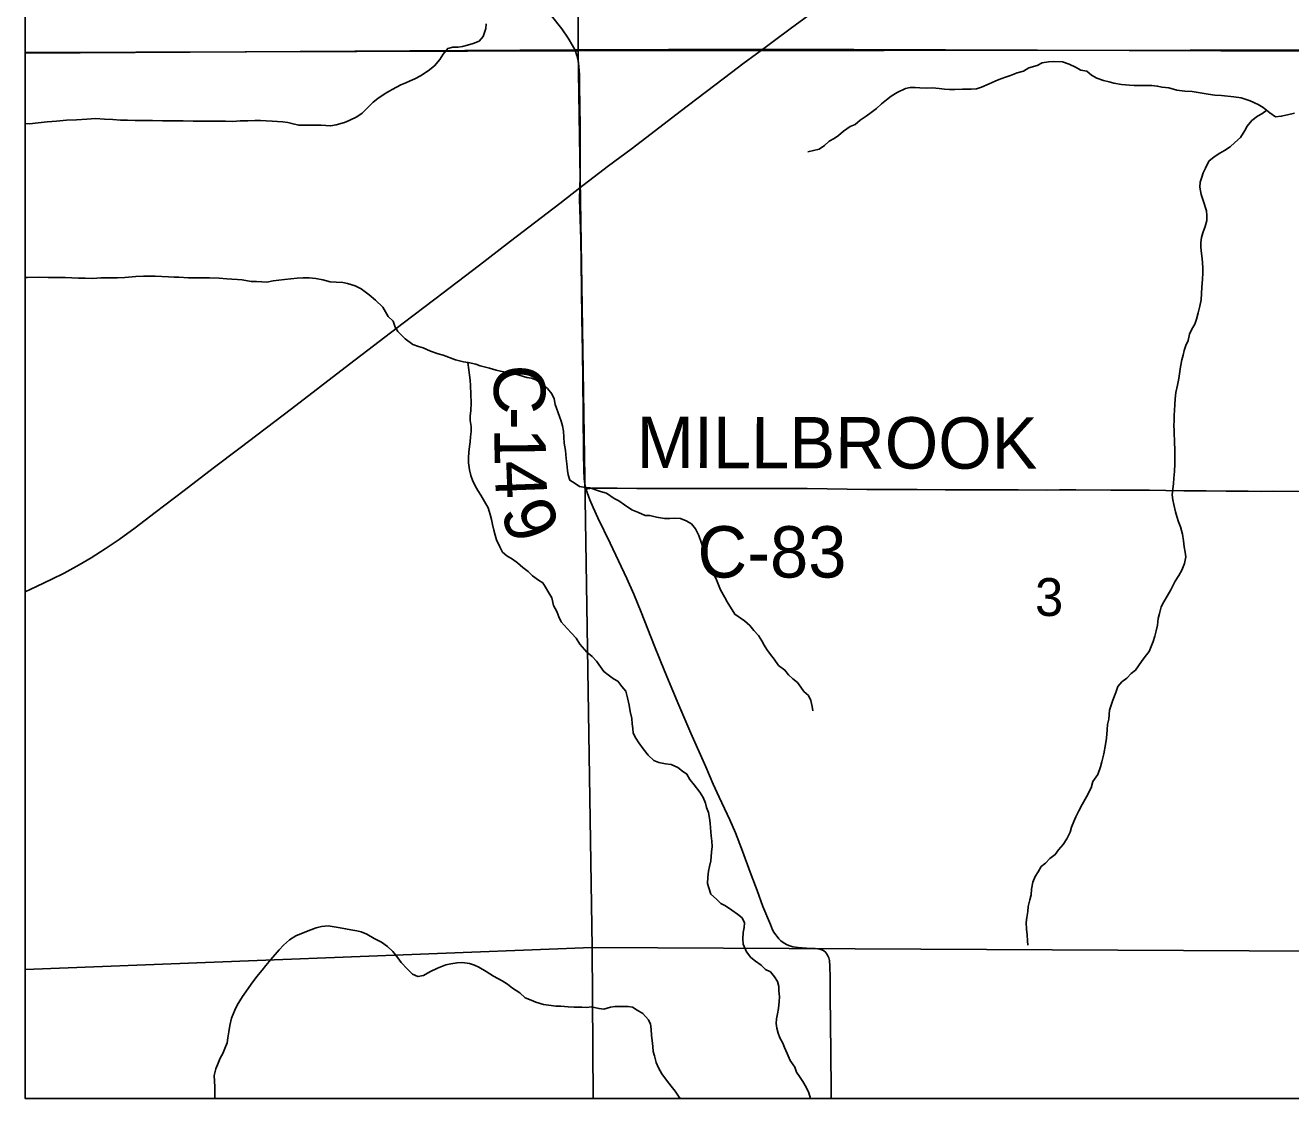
# Model space of a CAD drawing. Extents: x 0 to 34, y 0 to 22.
# Drawn here: x 2.1 to 3.5, y 14.1 to 15.287 of the extents above; entities that cross this region are included whole.
import ezdxf

# ---------------------------------------------------------------- set-up
doc = ezdxf.new("R2010")
doc.units = 0
for name, color, linetype in [('GM_X_County_Road', 7, 'Continuous'), ('GM_X_County_Road_Text', 7, 'Continuous'), ('GM_X_Minor_River', 7, 'Continuous'), ('GM_X_Section', 7, 'Continuous'), ('GM_X_Section_Text', 7, 'Continuous'), ('GM_X_State_Route', 7, 'Continuous'), ('GM_X_Township_Road', 7, 'Continuous'), ('GM_X_Unincorporated', 7, 'Continuous'), ('SH_Data', 7, 'Continuous')]:
    doc.layers.add(name, color=color, linetype=linetype)

msp = doc.modelspace()

# ---------------------------------------------------------------- linework, layer by layer
at = {"layer": 'GM_X_County_Road'}
for points in [[(2.708, 15.2591), (2.7053, 15.2645), (2.7005, 15.2725), (2.6934, 15.2826), (2.682, 15.2973)], [(2.7134, 15.1071), (2.7138, 15.1191), (2.7138, 15.1302), (2.7136, 15.1426), (2.7136, 15.1737), (2.7133, 15.1984), (2.713, 15.2197), (2.7128, 15.2321), (2.7124, 15.2413), (2.7115, 15.2474), (2.7101, 15.2533), (2.708, 15.2591)], [(2.7201, 14.774), (2.7197, 14.776), (2.7188, 14.7798), (2.718, 14.7854), (2.7176, 14.7951), (2.7172, 14.8137), (2.7169, 14.8573), (2.7167, 14.8946), (2.7161, 14.9257), (2.7157, 14.963), (2.7148, 15.0252), (2.7143, 15.05), (2.713, 15.094), (2.7134, 15.1071)], [(2.7201, 14.774), (2.7267, 14.7749), (2.7359, 14.775), (2.7545, 14.7749), (2.7762, 14.7747), (2.8352, 14.7747), (2.86, 14.7746), (2.8786, 14.7746), (2.9065, 14.7747), (2.9307, 14.7747), (2.9461, 14.7747), (2.9648, 14.7744), (3.0089, 14.7738), (3.0306, 14.7734), (3.0585, 14.7733), (3.071, 14.7733), (3.0865, 14.7733), (3.1175, 14.7731), (3.1393, 14.7732), (3.1734, 14.7732), (3.1983, 14.7732), (3.2293, 14.7729), (3.244, 14.773), (3.2618, 14.773), (3.3008, 14.7728), (3.3194, 14.7727), (3.3435, 14.7726), (3.3613, 14.7724), (3.3814, 14.7721), (3.3938, 14.772), (3.4062, 14.7719), (3.4282, 14.7717), (3.4527, 14.7716), (3.4673, 14.7714), (3.48, 14.7716), (3.5224, 14.7711)], [(2.9913, 14.1), (2.9913, 14.1135), (2.9909, 14.1468), (2.9904, 14.1872), (2.9903, 14.209), (2.9901, 14.2214), (2.9901, 14.2338), (2.99, 14.2463), (2.9894, 14.2526), (2.9887, 14.2558), (2.9874, 14.2588), (2.9854, 14.2615), (2.9828, 14.2636), (2.9799, 14.2649), (2.9767, 14.2657), (2.9735, 14.266), (2.9642, 14.2665), (2.9549, 14.2671), (2.9488, 14.268), (2.9456, 14.2691), (2.9426, 14.2701), (2.9395, 14.2718), (2.9356, 14.2746), (2.9335, 14.2768), (2.9315, 14.2791), (2.9297, 14.2815), (2.928, 14.2841), (2.9266, 14.2868), (2.9241, 14.2924), (2.9159, 14.3125), (2.9094, 14.33), (2.9028, 14.3474), (2.8922, 14.3766), (2.8854, 14.3939), (2.8792, 14.4082), (2.8675, 14.4333), (2.8609, 14.4476), (2.8526, 14.4667), (2.836, 14.5039), (2.8227, 14.535), (2.8096, 14.5666), (2.8022, 14.5848), (2.7958, 14.6004), (2.781, 14.638), (2.7729, 14.6579), (2.7653, 14.6749), (2.7467, 14.7142), (2.7333, 14.7423), (2.7282, 14.7536), (2.7245, 14.7621), (2.7213, 14.7701), (2.7201, 14.774)]]:
    msp.add_lwpolyline(points, dxfattribs=at)
at = {"layer": 'GM_X_Minor_River'}
for points in [[(2.1, 15.1781), (2.1048, 15.1779), (2.1144, 15.1787), (2.1243, 15.1798), (2.1346, 15.1806), (2.1457, 15.1817), (2.1567, 15.1821), (2.1682, 15.1828), (2.1777, 15.1836), (2.1877, 15.1828), (2.1968, 15.1824), (2.2052, 15.1817), (2.2132, 15.1817), (2.2216, 15.1813), (2.2407, 15.1813), (2.2518, 15.1809), (2.2747, 15.1809), (2.2858, 15.1805), (2.2961, 15.1805), (2.3052, 15.1808), (2.3216, 15.1808), (2.3296, 15.1804), (2.3377, 15.1812), (2.3461, 15.1812), (2.3537, 15.1816), (2.3602, 15.1816), (2.3663, 15.1812), (2.3732, 15.1808), (2.3789, 15.1804), (2.385, 15.18), (2.3903, 15.1793), (2.3961, 15.1777), (2.4025, 15.1762), (2.4201, 15.1762), (2.4274, 15.1762), (2.4323, 15.1758), (2.4377, 15.1754), (2.4438, 15.1766), (2.4529, 15.1792), (2.4583, 15.1815), (2.4666, 15.1853), (2.4727, 15.1895), (2.4781, 15.1952), (2.4849, 15.2016), (2.4899, 15.2058), (2.4979, 15.2111), (2.5059, 15.2157), (2.5154, 15.221), (2.5208, 15.2229), (2.5257, 15.2252), (2.531, 15.2275), (2.5371, 15.2309), (2.5455, 15.2362), (2.5524, 15.2419), (2.5585, 15.2487), (2.5623, 15.2548), (2.5672, 15.2609), (2.5729, 15.2624), (2.5787, 15.2624), (2.5836, 15.2632), (2.589, 15.2647), (2.5955, 15.2666), (2.6019, 15.2693), (2.6065, 15.2742), (2.6095, 15.2833), (2.6099, 15.2883)], [(3.5039, 15.1896), (3.4959, 15.1877), (3.4891, 15.1862), (3.4826, 15.1855), (3.4765, 15.19), (3.4692, 15.1957), (3.4635, 15.1992), (3.4547, 15.2033), (3.4448, 15.2064), (3.4367, 15.2075), (3.423, 15.2091), (3.4157, 15.2095), (3.4081, 15.2106), (3.3993, 15.2121), (3.3905, 15.2133), (3.3825, 15.2137), (3.3738, 15.2148), (3.3646, 15.2175), (3.3573, 15.2182), (3.352, 15.2194), (3.3459, 15.2201), (3.3264, 15.2202), (3.3211, 15.2205), (3.3123, 15.2213), (3.3039, 15.2228), (3.2989, 15.2243), (3.2924, 15.2255), (3.2852, 15.2282), (3.2791, 15.2316), (3.2741, 15.2358), (3.2676, 15.2369), (3.2615, 15.2403), (3.2546, 15.2438), (3.247, 15.2464), (3.237, 15.2468), (3.2317, 15.2461), (3.2248, 15.2453), (3.2191, 15.2423), (3.21, 15.2396), (3.2039, 15.2358), (3.197, 15.2343), (3.1898, 15.2313), (3.184, 15.2294), (3.176, 15.2263), (3.1661, 15.2221), (3.1577, 15.2183), (3.152, 15.2164), (3.1463, 15.2161), (3.1364, 15.2161), (3.128, 15.2157), (3.1222, 15.2157), (3.1165, 15.2161), (3.1108, 15.2169), (3.1035, 15.2176), (3.0963, 15.2172), (3.0894, 15.2176), (3.0841, 15.218), (3.0787, 15.218), (3.0734, 15.2169), (3.0642, 15.2123), (3.0578, 15.2085), (3.0524, 15.2043), (3.0471, 15.1998), (3.0414, 15.1948), (3.0357, 15.1903), (3.03, 15.1861), (3.0235, 15.1819), (3.0178, 15.177), (3.0124, 15.1747), (3.0048, 15.1698), (2.9995, 15.1648), (2.9945, 15.1614), (2.9892, 15.1584), (2.9839, 15.1538), (2.9781, 15.1496), (2.9717, 15.1481), (2.9656, 15.1466)], [(3.4736, 15.1923), (3.473, 15.1927), (3.4677, 15.1889), (3.4627, 15.1862), (3.4566, 15.1813), (3.4513, 15.1752), (3.4487, 15.1703), (3.4441, 15.1627), (3.4376, 15.157), (3.4327, 15.1524), (3.4262, 15.1482), (3.4212, 15.1452), (3.4148, 15.1414), (3.409, 15.1364), (3.4052, 15.1288), (3.4026, 15.1235), (3.4011, 15.1186), (3.3996, 15.1133), (3.3992, 15.1076), (3.4007, 15.0996), (3.4027, 15.0931), (3.4065, 15.0817), (3.4069, 15.0764), (3.4069, 15.071), (3.405, 15.0642), (3.4024, 15.0574), (3.4008, 15.052), (3.4001, 15.0467), (3.4001, 15.0414), (3.4009, 15.0342), (3.4017, 15.0288), (3.4021, 15.0239), (3.4025, 15.0186), (3.4025, 15.0129), (3.4021, 15.0056), (3.4014, 14.9973), (3.401, 14.9901), (3.4006, 14.9832), (3.3991, 14.976), (3.3972, 14.9688), (3.3953, 14.9619), (3.3934, 14.9562), (3.3904, 14.9509), (3.3877, 14.9452), (3.3862, 14.9383), (3.3836, 14.9326), (3.3817, 14.9273), (3.3805, 14.922), (3.379, 14.9167), (3.3775, 14.9091), (3.3768, 14.9041), (3.3757, 14.8961), (3.3745, 14.8889), (3.3726, 14.8806), (3.3719, 14.8737), (3.3715, 14.8676), (3.3712, 14.8608), (3.3708, 14.8558), (3.3708, 14.8494), (3.3704, 14.8444), (3.3708, 14.8387), (3.3709, 14.8239), (3.3713, 14.819), (3.3713, 14.8018), (3.3709, 14.7935), (3.3702, 14.7859), (3.3698, 14.7802), (3.3691, 14.7737), (3.3683, 14.7676), (3.3691, 14.7619), (3.3703, 14.757), (3.3722, 14.7486), (3.3737, 14.7437), (3.3756, 14.7376), (3.3776, 14.7323), (3.3799, 14.7239), (3.381, 14.7167), (3.3818, 14.7102), (3.383, 14.7041), (3.3834, 14.6992), (3.3822, 14.6916), (3.3792, 14.6843), (3.3758, 14.6783), (3.3716, 14.6722), (3.367, 14.6627), (3.3629, 14.6554), (3.3591, 14.6494), (3.3564, 14.6437), (3.3545, 14.6364), (3.353, 14.6307), (3.3523, 14.6235), (3.3507, 14.6171), (3.3492, 14.6113), (3.3473, 14.6053), (3.3451, 14.5999), (3.3432, 14.5942), (3.3386, 14.5889), (3.3344, 14.5832), (3.3279, 14.5737), (3.323, 14.5699), (3.3184, 14.565)], [(2.1, 15.0079), (2.1026, 15.0079), (2.1144, 15.0083), (2.1251, 15.0079), (2.1442, 15.0079), (2.1587, 15.0072), (2.1663, 15.0071), (2.1747, 15.0068), (2.1835, 15.0075), (2.2018, 15.0075), (2.2102, 15.0079), (2.2224, 15.009), (2.2308, 15.0094), (2.2438, 15.0094), (2.2583, 15.0086), (2.2648, 15.0082), (2.2697, 15.0082), (2.2804, 15.0075), (2.3037, 15.0074), (2.3144, 15.0071), (2.3228, 15.0063), (2.3285, 15.0059), (2.3346, 15.0055), (2.34, 15.0051), (2.3499, 15.0036), (2.3556, 15.0036), (2.3617, 15.0032), (2.3671, 15.0028), (2.374, 15.004), (2.3865, 15.0055), (2.4007, 15.007), (2.4071, 15.0074), (2.414, 15.0074), (2.4213, 15.0066), (2.4289, 15.0051), (2.4373, 15.0032), (2.4438, 15.0028), (2.4511, 15.0024), (2.4564, 15.0013), (2.4648, 14.9986), (2.4713, 14.9952), (2.4805, 14.9887), (2.4874, 14.9826), (2.4954, 14.975), (2.5015, 14.9647), (2.5069, 14.9594), (2.5092, 14.9529), (2.5122, 14.948), (2.5203, 14.94), (2.5287, 14.9339), (2.5348, 14.9316), (2.5401, 14.9301), (2.5482, 14.9263), (2.5566, 14.9236), (2.5623, 14.9221), (2.5757, 14.9168), (2.5848, 14.9145), (2.5898, 14.9137), (2.5982, 14.9122), (2.6032, 14.9103), (2.6135, 14.9076), (2.6207, 14.9053), (2.6257, 14.9042), (2.631, 14.903), (2.636, 14.9023), (2.6425, 14.9011), (2.6547, 14.8973), (2.6597, 14.8966), (2.6654, 14.8943), (2.6719, 14.8897), (2.6777, 14.8851), (2.6822, 14.8794), (2.6849, 14.8737), (2.6861, 14.8673), (2.6907, 14.854), (2.6926, 14.849), (2.6942, 14.8437), (2.6953, 14.838), (2.6961, 14.8247), (2.6973, 14.8167), (2.6981, 14.8076), (2.6988, 14.8019), (2.6996, 14.7946), (2.7004, 14.7897), (2.7023, 14.7836), (2.708, 14.7802), (2.713, 14.7768), (2.7195, 14.7756)], [(2.5894, 14.9138), (2.5906, 14.9057), (2.5914, 14.8997), (2.5921, 14.8943), (2.5925, 14.8886), (2.5929, 14.8787), (2.593, 14.8692), (2.5926, 14.8605), (2.5922, 14.8548), (2.5922, 14.8498), (2.593, 14.843), (2.593, 14.8377), (2.5923, 14.8316), (2.5919, 14.8263), (2.5912, 14.8209), (2.5904, 14.8149), (2.5901, 14.8084), (2.5901, 14.8031), (2.5912, 14.7951), (2.5928, 14.789), (2.5947, 14.7837), (2.5974, 14.7776), (2.6004, 14.7723), (2.6039, 14.7673), (2.6077, 14.7601), (2.6119, 14.7532), (2.6142, 14.746), (2.6158, 14.7403), (2.6166, 14.7346), (2.6181, 14.7285), (2.6196, 14.7228), (2.6212, 14.7179), (2.625, 14.7099), (2.6277, 14.7042), (2.6327, 14.7), (2.6388, 14.6966), (2.6445, 14.6924), (2.6503, 14.6874), (2.656, 14.6829), (2.661, 14.6779), (2.6675, 14.6733), (2.6724, 14.6703), (2.6755, 14.6654), (2.6789, 14.6593), (2.6824, 14.6536), (2.6843, 14.6452), (2.6878, 14.6384), (2.6901, 14.6326), (2.6928, 14.6273), (2.6993, 14.6197), (2.7042, 14.6148), (2.7092, 14.6091), (2.7134, 14.6026), (2.7211, 14.5938), (2.7268, 14.5889), (2.7318, 14.5836), (2.736, 14.5775), (2.7398, 14.5722), (2.7448, 14.5687), (2.7505, 14.5642), (2.7555, 14.5615), (2.7597, 14.5558), (2.7643, 14.5505), (2.7659, 14.5432), (2.7678, 14.5349), (2.7689, 14.528), (2.7709, 14.5204), (2.7713, 14.5143), (2.772, 14.5094), (2.7724, 14.5041), (2.7751, 14.4984), (2.7786, 14.4934), (2.7832, 14.4866), (2.7889, 14.4797), (2.795, 14.474), (2.8008, 14.4717), (2.808, 14.4702), (2.8145, 14.4694), (2.8218, 14.466), (2.8267, 14.4622), (2.8317, 14.4588), (2.8351, 14.4527), (2.8397, 14.447), (2.8459, 14.439), (2.8497, 14.4329), (2.8524, 14.4268), (2.8535, 14.4219), (2.8555, 14.4162), (2.8566, 14.4101), (2.8574, 14.4044), (2.8578, 14.3994), (2.8586, 14.3907), (2.8594, 14.3846), (2.8597, 14.3789), (2.859, 14.3725), (2.8583, 14.3629), (2.8567, 14.3565), (2.8556, 14.3515), (2.8549, 14.3447), (2.8545, 14.3379), (2.856, 14.3329)], [(2.7195, 14.7756), (2.7245, 14.7752), (2.7363, 14.7714), (2.7428, 14.7695), (2.7512, 14.7634), (2.7566, 14.7608), (2.7627, 14.7566), (2.7707, 14.7509), (2.7783, 14.7482), (2.7856, 14.7448), (2.7906, 14.7448), (2.7982, 14.7429), (2.807, 14.7413), (2.8127, 14.7413), (2.8177, 14.7417), (2.8245, 14.7413), (2.831, 14.7387), (2.8368, 14.7356), (2.8414, 14.7299), (2.8448, 14.7227), (2.8502, 14.7078), (2.8529, 14.6995), (2.8552, 14.6942), (2.8571, 14.6877), (2.8594, 14.6824), (2.8636, 14.6755), (2.869, 14.6626), (2.8736, 14.6542), (2.8763, 14.6493), (2.8847, 14.6356), (2.8954, 14.6283), (2.9012, 14.623), (2.9057, 14.6177), (2.9111, 14.612), (2.9145, 14.6063), (2.9172, 14.6013), (2.9203, 14.5964), (2.9241, 14.5911), (2.9283, 14.5857), (2.9329, 14.5789), (2.9402, 14.5739), (2.944, 14.5686), (2.949, 14.564), (2.954, 14.5602), (2.9578, 14.5549), (2.9612, 14.55), (2.9662, 14.5458), (2.9689, 14.5401), (2.9704, 14.5336), (2.9712, 14.5287)], [(3.3184, 14.565), (3.3127, 14.5608), (3.3085, 14.5555), (3.3062, 14.549), (3.3028, 14.5406), (3.3009, 14.5349), (3.299, 14.5296), (3.2983, 14.5197), (3.2968, 14.5137), (3.2964, 14.5076), (3.2957, 14.4984), (3.2949, 14.4916), (3.293, 14.4813), (3.2908, 14.4722), (3.2893, 14.4669), (3.2862, 14.4585), (3.2809, 14.4505), (3.279, 14.4437), (3.2737, 14.4338), (3.2691, 14.4251), (3.2653, 14.4182), (3.2619, 14.4114), (3.2596, 14.4064), (3.257, 14.4), (3.2555, 14.3947), (3.2521, 14.3871), (3.2479, 14.381), (3.2429, 14.3749), (3.2391, 14.3699), (3.233, 14.3654), (3.2285, 14.3604), (3.2235, 14.3566), (3.2201, 14.3509), (3.217, 14.3456), (3.2144, 14.3392), (3.2129, 14.3316), (3.2125, 14.3255), (3.211, 14.3198), (3.2091, 14.3125), (3.2087, 14.3068), (3.2076, 14.3004), (3.2069, 14.2947), (3.2073, 14.2874), (3.208, 14.281), (3.2084, 14.2745), (3.2088, 14.2696)], [(2.856, 14.3329), (2.8583, 14.3261), (2.8645, 14.3204), (2.8694, 14.3158), (2.8744, 14.3131), (2.8813, 14.3082), (2.8878, 14.304), (2.8928, 14.2998), (2.8954, 14.2945), (2.8951, 14.2892), (2.8939, 14.2838), (2.8936, 14.2766), (2.894, 14.2709), (2.8978, 14.2622), (2.9024, 14.2561), (2.9078, 14.2519), (2.9139, 14.2477), (2.9188, 14.2428), (2.9242, 14.2401), (2.9288, 14.2348), (2.9318, 14.2294), (2.9334, 14.2241), (2.9334, 14.2192), (2.9342, 14.2127), (2.9338, 14.2074), (2.9331, 14.1998), (2.9319, 14.1937), (2.9308, 14.1884), (2.9304, 14.183), (2.9312, 14.1781), (2.9327, 14.1724), (2.9347, 14.1671), (2.9377, 14.1614), (2.9397, 14.1564), (2.9427, 14.15), (2.9458, 14.1423), (2.9512, 14.1347), (2.9531, 14.1294), (2.9561, 14.1245), (2.96, 14.1188), (2.9638, 14.1127), (2.9665, 14.1066), (2.9683, 14.1)], [(2.3095, 14.1), (2.3097, 14.1032), (2.3097, 14.1131), (2.3093, 14.1195), (2.3089, 14.1256), (2.3108, 14.1328), (2.3134, 14.1393), (2.3157, 14.1446), (2.3183, 14.1499), (2.3206, 14.1553), (2.3233, 14.1617), (2.324, 14.1674), (2.3252, 14.1739), (2.3263, 14.1807), (2.3282, 14.1891), (2.3316, 14.1979), (2.3343, 14.2032), (2.3403, 14.2131), (2.3438, 14.218), (2.3498, 14.2264), (2.3559, 14.2351), (2.362, 14.2419), (2.3662, 14.2473), (2.3715, 14.2537), (2.3807, 14.2644), (2.3856, 14.2697), (2.3921, 14.2754), (2.3993, 14.2799), (2.4092, 14.2841), (2.4157, 14.2868), (2.4218, 14.2887), (2.4275, 14.2902), (2.4348, 14.291), (2.4482, 14.289), (2.4543, 14.2879), (2.46, 14.2868), (2.4665, 14.2856), (2.4715, 14.2845), (2.4776, 14.2818), (2.486, 14.2772), (2.494, 14.273), (2.5005, 14.2681), (2.5066, 14.2628), (2.512, 14.2555), (2.5158, 14.2506), (2.5227, 14.243), (2.5284, 14.2377), (2.5342, 14.235), (2.5403, 14.2361), (2.5475, 14.2403), (2.5559, 14.2441), (2.565, 14.2479), (2.5708, 14.249), (2.5776, 14.2502), (2.583, 14.2506), (2.5914, 14.2494), (2.5967, 14.2475), (2.6017, 14.2452), (2.6097, 14.2407), (2.6177, 14.2353)], [(2.6177, 14.2353), (2.6273, 14.2304), (2.6334, 14.2266), (2.6388, 14.222), (2.6468, 14.2171), (2.6529, 14.2113), (2.6594, 14.2087), (2.6648, 14.2068), (2.6732, 14.2041), (2.6816, 14.203), (2.6869, 14.2022), (2.6922, 14.2022), (2.7006, 14.2014), (2.7071, 14.201), (2.7155, 14.201), (2.7209, 14.2007), (2.7258, 14.2014), (2.7346, 14.1995), (2.74, 14.1991), (2.7472, 14.201), (2.7522, 14.2018), (2.7667, 14.2018), (2.7716, 14.201), (2.7766, 14.198), (2.7831, 14.1942), (2.7892, 14.1873), (2.7915, 14.1824), (2.7923, 14.1767), (2.7927, 14.1698), (2.7935, 14.1641), (2.7942, 14.1576), (2.7946, 14.1523), (2.7958, 14.1474), (2.7977, 14.1398), (2.8004, 14.1341), (2.8039, 14.1276), (2.8092, 14.1204), (2.8142, 14.1139), (2.8188, 14.1082), (2.8226, 14.1029), (2.8244, 14.1)]]:
    msp.add_lwpolyline(points, dxfattribs=at)
at = {"layer": 'GM_X_Section'}
for points in [[(2.7146, 16.2714), (3.7413, 16.2718), (3.7269, 15.2595), (2.7116, 15.2583)], [(3.7269, 15.2595), (3.7425, 15.2596), (3.7447, 14.2621), (2.727, 14.267), (2.7116, 15.2583)]]:
    msp.add_lwpolyline(points, close=True, dxfattribs=at)
at = {"layer": 'GM_X_State_Route'}
for points in [[(2.9152, 15.2599), (2.9285, 15.2698), (2.946, 15.2827), (2.9666, 15.2977)], [(2.7166, 15.1095), (2.7229, 15.1144), (2.7452, 15.1312), (2.77, 15.1499), (2.7923, 15.1668), (2.8244, 15.1912), (2.8812, 15.2345), (2.8936, 15.2439), (2.9086, 15.255), (2.9152, 15.2599)], [(2.1, 14.6605), (2.1123, 14.6663), (2.1292, 14.6743), (2.1431, 14.6811), (2.1594, 14.69), (2.1728, 14.6979), (2.1885, 14.7078), (2.2039, 14.7183), (2.2215, 14.731), (2.2437, 14.7479), (2.2758, 14.7724), (2.3078, 14.7971), (2.3376, 14.8196), (2.3945, 14.8628), (2.4584, 14.9121), (2.518, 14.9573), (2.5528, 14.984), (2.5776, 15.0028), (2.6023, 15.0215), (2.622, 15.0366), (2.6368, 15.0479), (2.6911, 15.0895), (2.7134, 15.1071), (2.7166, 15.1095)]]:
    msp.add_lwpolyline(points, dxfattribs=at)
at = {"layer": 'GM_X_Township_Road'}
for points in [[(2.1, 20.9), (2.1, 15.2557), (2.7077, 15.2596), (2.915, 15.2604), (3.727, 15.2572), (4.7402, 15.2622)], [(4.7402, 15.2622), (3.727, 15.2572), (2.915, 15.2604), (2.7077, 15.2596), (2.1, 15.2557), (2.1, 14.1), (5.7705, 14.1)]]:
    msp.add_lwpolyline(points, dxfattribs=at)
at = {"layer": 'GM_X_Unincorporated'}
for points in [[(2.1, 16.2714), (2.1, 15.2567), (2.7116, 15.2583), (2.7146, 16.2714)], [(2.1, 15.2567), (2.1, 14.2427), (2.727, 14.267), (2.7116, 15.2583)], [(2.1, 14.2427), (2.1, 14.1), (2.7279, 14.1), (2.727, 14.267)], [(2.7279, 14.1), (3.7463, 14.1), (3.7447, 14.2621), (2.727, 14.267)]]:
    msp.add_lwpolyline(points, close=True, dxfattribs=at)
at = {"layer": 'SH_Data'}
for p, q in [((2.1, 20.9), (2.1, 14.1)), ((2.1, 14.1), (8.9, 14.1)), ((2.1, 14.1), (2.1, 14.1))]:
    msp.add_line(p, q, dxfattribs=at)

# ---------------------------------------------------------------- texts
at = {"layer": 'GM_X_County_Road_Text'}
for s, height, rotation, p in [('C', 0.0568, 270.4391, (2.6181, 14.9113)), ('-', 0.0568, 270.4632, (2.6185, 14.8647)), ('MILLBROOK', 0.05682, 359.885, (2.7761, 14.7972)), ('1', 0.0568, 270.5792, (2.6187, 14.8412)), ('4', 0.0568, 272.1153, (2.619, 14.8045)), ('9', 0.0568, 291.2073, (2.6245, 14.7494)), ('C-83', 0.05682, 0, (2.8435, 14.6761))]:
    msp.add_text(s, height=height, rotation=rotation, dxfattribs=at).set_placement(p)
at = {"layer": 'GM_X_Section_Text'}
msp.add_text('3', height=0.0419, rotation=0, dxfattribs=at).set_placement((3.2168, 14.6336))

doc.saveas('drawing.dxf')
